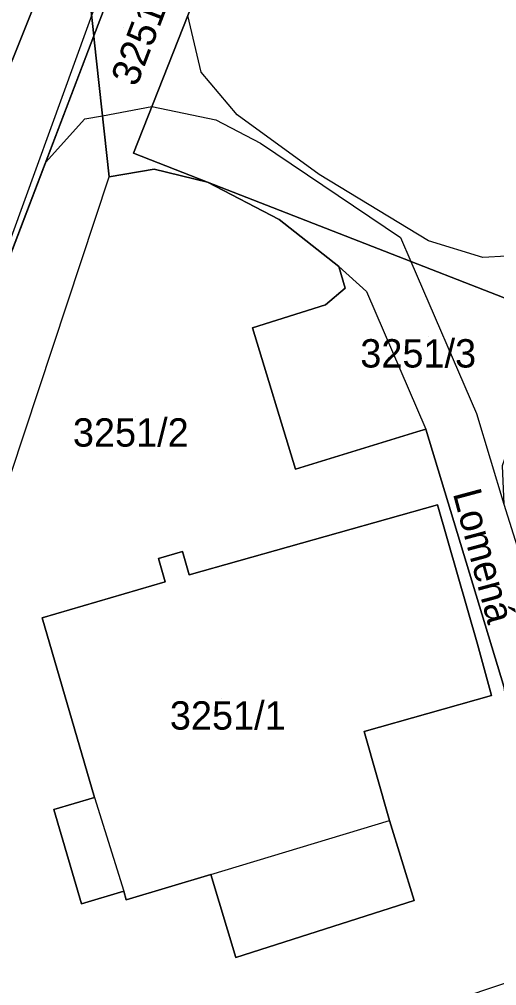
# Model space of a CAD drawing. Extents: x -264070 to -262271, y -1238894 to -1238141.
# Drawn here: x -262462.3 to -262428.6, y -1238623 to -1238554.9 of the extents above; entities that cross this region are included whole.
import ezdxf

# ---------------------------------------------------------------- set-up
doc = ezdxf.new("R2010")
doc.units = 0
for name, color, linetype in [('body_kn', 7, 'Continuous'), ('kladpar_druhypozemkov', 7, 'Continuous'), ('kladpar_hranice', 7, 'Continuous'), ('kladpar_parcelnecisla', 7, 'Continuous'), ('kladpar_plochy', 7, 'Continuous'), ('popisy', 7, 'Continuous'), ('tarchy_linie', 7, 'Continuous'), ('zappar_hrandruhpozemk', 7, 'Continuous')]:
    doc.layers.add(name, color=color, linetype=linetype)

msp = doc.modelspace()

# ---------------------------------------------------------------- linework, layer by layer
at = {"layer": 'body_kn'}
for p, q in [((-262457.05, -1238556.02), (-262457.05, -1238556.02)), ((-262457.02, -1238556.3), (-262457.02, -1238556.3)), ((-262449.46, -1238558.58), (-262449.46, -1238558.58)), ((-262452.94, -1238561), (-262452.94, -1238561)), ((-262452.94, -1238561), (-262452.94, -1238561)), ((-262457.67, -1238561.88), (-262457.67, -1238561.88)), ((-262456.44, -1238561.65), (-262456.44, -1238561.65)), ((-262446.92, -1238561.59), (-262446.92, -1238561.59)), ((-262448.42, -1238561.95), (-262448.42, -1238561.95)), ((-262445.27, -1238563.58), (-262445.27, -1238563.58)), ((-262454.25, -1238564.3), (-262454.25, -1238564.3)), ((-262460.46, -1238564.95), (-262460.46, -1238564.95)), ((-262460.46, -1238564.96), (-262460.46, -1238564.96)), ((-262455.97, -1238565.95), (-262455.97, -1238565.95)), ((-262452.78, -1238565.42), (-262452.78, -1238565.42)), ((-262452.78, -1238565.42), (-262452.78, -1238565.42)), ((-262441.14, -1238565.8), (-262441.14, -1238565.8)), ((-262449.01, -1238566.34), (-262449.01, -1238566.34)), ((-262443.95, -1238568.96), (-262443.95, -1238568.96)), ((-262435.39, -1238570.24), (-262435.39, -1238570.24)), ((-262433.42, -1238570.48), (-262433.42, -1238570.48)), ((-262434.66, -1238571.93), (-262434.66, -1238571.93)), ((-262434.66, -1238571.93), (-262434.66, -1238571.93)), ((-262429.58, -1238571.66), (-262429.58, -1238571.66)), ((-262439.74, -1238572.28), (-262439.74, -1238572.28)), ((-262439.74, -1238572.28), (-262439.74, -1238572.28)), ((-262439.3, -1238573.82), (-262439.3, -1238573.82)), ((-262437.8, -1238574.04), (-262437.8, -1238574.04)), ((-262440.68, -1238574.98), (-262440.68, -1238574.98)), ((-262445.83, -1238576.62), (-262445.83, -1238576.62)), ((-262430.03, -1238582.65), (-262430.03, -1238582.65)), ((-262433.61, -1238583.75), (-262433.61, -1238583.75)), ((-262434.23, -1238583.94), (-262434.23, -1238583.94)), ((-262442.8, -1238586.57), (-262442.8, -1238586.57)), ((-262432.77, -1238589.1), (-262432.77, -1238589.1)), ((-262432.77, -1238589.1), (-262432.77, -1238589.1)), ((-262450.77, -1238592.38), (-262450.77, -1238592.38)), ((-262452.48, -1238592.88), (-262452.48, -1238592.88)), ((-262452, -1238594.52), (-262452, -1238594.52)), ((-262450.3, -1238594.03), (-262450.3, -1238594.03)), ((-262460.7, -1238597.07), (-262460.7, -1238597.07)), ((-262429.94, -1238598.92), (-262429.94, -1238598.92)), ((-262428.97, -1238602.54), (-262428.97, -1238602.54)), ((-262437.95, -1238605.08), (-262437.95, -1238605.08)), ((-262456.99, -1238609.74), (-262456.99, -1238609.74)), ((-262456.99, -1238609.74), (-262456.99, -1238609.74)), ((-262459.86, -1238610.58), (-262459.86, -1238610.58)), ((-262436.17, -1238611.35), (-262436.17, -1238611.35)), ((-262448.78, -1238615.16), (-262448.78, -1238615.16)), ((-262448.78, -1238615.16), (-262448.78, -1238615.16)), ((-262454.93, -1238616.35), (-262454.93, -1238616.35)), ((-262454.75, -1238616.96), (-262454.75, -1238616.96)), ((-262434.42, -1238617), (-262434.42, -1238617)), ((-262457.91, -1238617.23), (-262457.91, -1238617.23)), ((-262447.01, -1238621.02), (-262447.01, -1238621.02))]:
    msp.add_line(p, q, dxfattribs=at)
at = {"layer": 'kladpar_druhypozemkov'}
for p, q in [((-262454.95, -1238555.4), (-262454.95, -1238555.4)), ((-262433.44, -1238577.25), (-262433.44, -1238577.25)), ((-262454.1, -1238582.87), (-262454.1, -1238582.87)), ((-262448, -1238602.75), (-262448, -1238602.75))]:
    msp.add_line(p, q, dxfattribs=at)
at = {"layer": 'kladpar_hranice'}
msp.add_line((-262455.97, -1238565.95), (-262452.78, -1238565.42), dxfattribs=at)
for points in [[(-262385.51, -1238525.08), (-262381.54, -1238524.51), (-262381.19, -1238524.41), (-262368.91, -1238564.9), (-262376.4, -1238567.23), (-262385.89, -1238570.19), (-262395.66, -1238573.25), (-262407.03, -1238576.84), (-262409.67, -1238577.62), (-262412.32, -1238578.41), (-262414.97, -1238579.19), (-262415.58, -1238579.37), (-262449.01, -1238566.34), (-262454.25, -1238564.3), (-262450.4, -1238554.59), (-262449.19, -1238551.55), (-262448.34, -1238549.41), (-262447.4, -1238547.04), (-262435.35, -1238516.46), (-262432.64, -1238515.23), (-262432.61, -1238515.21), (-262423.64, -1238511.36), (-262419.15, -1238510.39), (-262385.51, -1238525.08)], [(-262440.23, -1238516.83), (-262432.95, -1238514.36), (-262432.64, -1238515.23), (-262435.35, -1238516.46), (-262447.4, -1238547.04), (-262448.34, -1238549.41), (-262453.85, -1238547.64), (-262457.05, -1238556.02), (-262457.57, -1238551.22), (-262449.03, -1238530.28), (-262449.69, -1238520.04), (-262440.23, -1238516.83)], [(-262460.02, -1238550.8), (-262465.64, -1238564.74), (-262471.5, -1238580.77), (-262501.65, -1238568.73), (-262500.98, -1238566.78), (-262497.46, -1238557.4), (-262491.58, -1238559.47), (-262493.98, -1238564.62), (-262485.29, -1238567.72), (-262486.27, -1238570.21), (-262480.22, -1238572.58), (-262477.02, -1238570.08), (-262478.15, -1238568.69), (-262476.18, -1238566.98), (-262477.24, -1238565.67), (-262471.3, -1238551.54), (-262479.46, -1238548.39), (-262481.46, -1238553.53), (-262488.7, -1238550.71), (-262486.42, -1238544.86), (-262486.13, -1238545), (-262484.82, -1238541.61), (-262460.02, -1238550.8)], [(-262453.85, -1238547.64), (-262448.34, -1238549.41), (-262449.19, -1238551.55), (-262450.4, -1238554.59), (-262454.25, -1238564.3), (-262449.01, -1238566.34), (-262452.78, -1238565.42), (-262455.97, -1238565.95), (-262457.02, -1238556.3), (-262457.05, -1238556.02), (-262453.85, -1238547.64)], [(-262457.57, -1238551.22), (-262457.05, -1238556.02), (-262467.16, -1238582.5), (-262471.5, -1238580.77), (-262465.64, -1238564.74), (-262460.02, -1238550.8)], [(-262452.78, -1238565.42), (-262449.01, -1238566.34), (-262443.95, -1238568.96), (-262439.74, -1238572.28), (-262439.3, -1238573.82), (-262440.68, -1238574.98), (-262445.83, -1238576.62), (-262442.8, -1238586.57), (-262434.23, -1238583.94), (-262433.61, -1238583.75), (-262428.07, -1238601.98), (-262425.26, -1238621.92), (-262467.6, -1238636.18), (-262471.26, -1238623.01), (-262473.55, -1238615.3), (-262476.15, -1238606.48), (-262474.77, -1238602.89), (-262471.24, -1238593.21), (-262468.92, -1238587.13), (-262467.16, -1238582.5), (-262457.05, -1238556.02), (-262457.02, -1238556.3), (-262455.97, -1238565.95)], [(-262415.58, -1238579.37), (-262417.51, -1238582.03), (-262421.57, -1238582.77), (-262422.29, -1238580.49), (-262425.44, -1238581.85), (-262427.39, -1238584), (-262428.22, -1238586.35), (-262428.09, -1238589.05), (-262424.37, -1238600.86), (-262421.43, -1238620.6), (-262425.26, -1238621.92), (-262428.07, -1238601.98), (-262433.61, -1238583.75), (-262434.23, -1238583.94), (-262442.8, -1238586.57), (-262445.83, -1238576.62), (-262440.68, -1238574.98), (-262439.3, -1238573.82), (-262439.74, -1238572.28), (-262443.95, -1238568.96), (-262449.01, -1238566.34), (-262415.58, -1238579.37)], [(-262450.3, -1238594.03), (-262450.77, -1238592.38), (-262452.48, -1238592.88), (-262452, -1238594.52), (-262460.7, -1238597.07), (-262456.99, -1238609.74), (-262459.86, -1238610.58), (-262457.91, -1238617.23), (-262454.93, -1238616.35), (-262454.75, -1238616.96), (-262448.78, -1238615.16), (-262447.01, -1238621.02), (-262434.42, -1238617), (-262436.17, -1238611.35), (-262437.95, -1238605.08), (-262428.97, -1238602.54), (-262429.94, -1238598.92), (-262432.77, -1238589.1), (-262450.3, -1238594.03)], [(-262432.77, -1238589.1), (-262429.94, -1238598.92), (-262428.97, -1238602.54), (-262437.95, -1238605.08), (-262436.17, -1238611.35), (-262434.42, -1238617), (-262447.01, -1238621.02), (-262448.78, -1238615.16), (-262454.75, -1238616.96), (-262454.93, -1238616.35), (-262457.91, -1238617.23), (-262459.86, -1238610.58), (-262456.99, -1238609.74), (-262460.7, -1238597.07), (-262452, -1238594.52), (-262452.48, -1238592.88), (-262450.77, -1238592.38), (-262450.3, -1238594.03), (-262432.77, -1238589.1)]]:
    msp.add_lwpolyline(points, dxfattribs=at)
at = {"layer": 'kladpar_plochy'}
for p, q in [((-262467.16, -1238582.5), (-262457.05, -1238556.02)), ((-262457.05, -1238556.02), (-262457.02, -1238556.3)), ((-262457.02, -1238556.3), (-262455.97, -1238565.95)), ((-262455.97, -1238565.95), (-262452.78, -1238565.42)), ((-262452.78, -1238565.42), (-262449.01, -1238566.34)), ((-262449.01, -1238566.34), (-262443.95, -1238568.96)), ((-262443.95, -1238568.96), (-262439.74, -1238572.28)), ((-262439.74, -1238572.28), (-262439.3, -1238573.82)), ((-262439.3, -1238573.82), (-262440.68, -1238574.98)), ((-262440.68, -1238574.98), (-262445.83, -1238576.62)), ((-262445.83, -1238576.62), (-262442.8, -1238586.57)), ((-262434.23, -1238583.94), (-262433.61, -1238583.75)), ((-262433.61, -1238583.75), (-262428.07, -1238601.98)), ((-262442.8, -1238586.57), (-262434.23, -1238583.94)), ((-262432.77, -1238589.1), (-262450.3, -1238594.03)), ((-262429.94, -1238598.92), (-262432.77, -1238589.1)), ((-262450.77, -1238592.38), (-262452.48, -1238592.88)), ((-262450.3, -1238594.03), (-262450.77, -1238592.38)), ((-262452.48, -1238592.88), (-262452, -1238594.52)), ((-262452, -1238594.52), (-262460.7, -1238597.07)), ((-262460.7, -1238597.07), (-262456.99, -1238609.74)), ((-262428.97, -1238602.54), (-262429.94, -1238598.92)), ((-262437.95, -1238605.08), (-262428.97, -1238602.54)), ((-262436.17, -1238611.35), (-262437.95, -1238605.08)), ((-262456.99, -1238609.74), (-262459.86, -1238610.58)), ((-262459.86, -1238610.58), (-262457.91, -1238617.23)), ((-262434.42, -1238617), (-262436.17, -1238611.35)), ((-262454.75, -1238616.96), (-262448.78, -1238615.16)), ((-262448.78, -1238615.16), (-262447.01, -1238621.02)), ((-262457.91, -1238617.23), (-262454.93, -1238616.35)), ((-262454.93, -1238616.35), (-262454.75, -1238616.96)), ((-262447.01, -1238621.02), (-262434.42, -1238617))]:
    msp.add_line(p, q, dxfattribs=at)
for points in [[(-262385.51, -1238525.08), (-262381.54, -1238524.51), (-262381.19, -1238524.41), (-262368.91, -1238564.9), (-262376.4, -1238567.23), (-262385.89, -1238570.19), (-262395.66, -1238573.25), (-262407.03, -1238576.84), (-262409.67, -1238577.62), (-262412.32, -1238578.41), (-262414.97, -1238579.19), (-262415.58, -1238579.37), (-262449.01, -1238566.34), (-262454.25, -1238564.3), (-262450.4, -1238554.59), (-262449.19, -1238551.55), (-262448.34, -1238549.41), (-262447.4, -1238547.04), (-262435.35, -1238516.46), (-262432.64, -1238515.23), (-262432.61, -1238515.21), (-262423.64, -1238511.36), (-262419.15, -1238510.39)], [(-262440.23, -1238516.83), (-262432.95, -1238514.36), (-262432.64, -1238515.23), (-262435.35, -1238516.46), (-262447.4, -1238547.04), (-262448.34, -1238549.41), (-262453.85, -1238547.64), (-262457.05, -1238556.02), (-262457.57, -1238551.22), (-262449.03, -1238530.28), (-262449.69, -1238520.04)], [(-262460.02, -1238550.8), (-262465.64, -1238564.74), (-262471.5, -1238580.77), (-262501.65, -1238568.73), (-262500.98, -1238566.78), (-262497.46, -1238557.4), (-262491.58, -1238559.47), (-262493.98, -1238564.62), (-262485.29, -1238567.72), (-262486.27, -1238570.21), (-262480.22, -1238572.58), (-262477.02, -1238570.08), (-262478.15, -1238568.69), (-262476.18, -1238566.98), (-262477.24, -1238565.67), (-262471.3, -1238551.54), (-262479.46, -1238548.39), (-262481.46, -1238553.53), (-262488.7, -1238550.71), (-262486.42, -1238544.86), (-262486.13, -1238545), (-262484.82, -1238541.61)], [(-262453.85, -1238547.64), (-262448.34, -1238549.41), (-262449.19, -1238551.55), (-262450.4, -1238554.59), (-262454.25, -1238564.3), (-262449.01, -1238566.34), (-262452.78, -1238565.42), (-262455.97, -1238565.95), (-262457.02, -1238556.3), (-262457.05, -1238556.02)], [(-262415.58, -1238579.37), (-262417.51, -1238582.03), (-262421.57, -1238582.77), (-262422.29, -1238580.49), (-262425.44, -1238581.85), (-262427.39, -1238584), (-262428.22, -1238586.35), (-262428.09, -1238589.05), (-262424.37, -1238600.86), (-262421.43, -1238620.6), (-262425.26, -1238621.92), (-262428.07, -1238601.98), (-262433.61, -1238583.75), (-262434.23, -1238583.94), (-262442.8, -1238586.57), (-262445.83, -1238576.62), (-262440.68, -1238574.98), (-262439.3, -1238573.82), (-262439.74, -1238572.28), (-262443.95, -1238568.96), (-262449.01, -1238566.34)], [(-262432.77, -1238589.1), (-262429.94, -1238598.92), (-262428.97, -1238602.54), (-262437.95, -1238605.08), (-262436.17, -1238611.35), (-262434.42, -1238617), (-262447.01, -1238621.02), (-262448.78, -1238615.16), (-262454.75, -1238616.96), (-262454.93, -1238616.35), (-262457.91, -1238617.23), (-262459.86, -1238610.58), (-262456.99, -1238609.74), (-262460.7, -1238597.07), (-262452, -1238594.52), (-262452.48, -1238592.88), (-262450.77, -1238592.38), (-262450.3, -1238594.03)]]:
    msp.add_lwpolyline(points, close=True, dxfattribs=at)
msp.add_lwpolyline([(-262457.57, -1238551.22), (-262457.05, -1238556.02), (-262467.16, -1238582.5), (-262471.5, -1238580.77), (-262465.64, -1238564.74), (-262460.02, -1238550.8)], dxfattribs=at)
at = {"layer": 'tarchy_linie'}
for points in [[(-262453.85, -1238547.64), (-262457.05, -1238556.02), (-262460.46, -1238564.96), (-262467.16, -1238582.5), (-262467.34, -1238582.43), (-262453.87, -1238545.42)], [(-262460.46, -1238564.95), (-262457.67, -1238561.88), (-262456.44, -1238561.65), (-262452.94, -1238561)], [(-262452.94, -1238561), (-262448.42, -1238561.95), (-262445.27, -1238563.58), (-262435.39, -1238570.24), (-262434.66, -1238571.93)], [(-262469.38, -1238588.33), (-262463.91, -1238589.92), (-262455.97, -1238565.95)], [(-262434.66, -1238571.93), (-262430.03, -1238582.65), (-262428.09, -1238589.05)], [(-262439.74, -1238572.28), (-262437.8, -1238574.04), (-262433.61, -1238583.75)]]:
    msp.add_lwpolyline(points, dxfattribs=at)
at = {"layer": 'zappar_hrandruhpozemk'}
for p, q in [((-262456.99, -1238609.74), (-262454.93, -1238616.35)), ((-262448.78, -1238615.16), (-262436.17, -1238611.35))]:
    msp.add_line(p, q, dxfattribs=at)
msp.add_lwpolyline([(-262420.91, -1238570.08), (-262426.24, -1238571.45), (-262429.58, -1238571.66), (-262433.42, -1238570.48), (-262441.14, -1238565.8), (-262446.92, -1238561.59), (-262449.46, -1238558.58), (-262450.4, -1238554.59)], dxfattribs=at)

# ---------------------------------------------------------------- texts
at = {"layer": 'kladpar_parcelnecisla'}
msp.add_text('3251/4', height=2, rotation=69, dxfattribs=at).set_placement((-262454.025, -1238559.672))
for s, p in [('3251/3', (-262438.227, -1238579.41)), ('3251/2', (-262458.521, -1238584.99)), ('3251/1', (-262451.675, -1238604.95))]:
    msp.add_text(s, height=2, dxfattribs=at).set_placement(p)
at = {"layer": 'popisy'}
msp.add_text('Lomená', height=2, rotation=285, dxfattribs=at).set_placement((-262431.703, -1238588.277))

doc.saveas('drawing.dxf')
